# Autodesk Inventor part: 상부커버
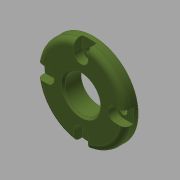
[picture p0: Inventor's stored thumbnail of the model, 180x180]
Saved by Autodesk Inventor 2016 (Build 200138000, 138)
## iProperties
Created: 2019-01
Part Number: 상부커버
Material: 알루미늄 6061
Document SubType Name: Modeling
Designer: mduedu
Density: 2.71 g/cm^3
Appearance: 올리브 녹색
Mass: 28.8858 g
Surface Area: 53.2237 cm^2
Volume: 10.659 cm^3
Author: mduedu
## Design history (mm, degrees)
sketch "스케치1"
  geometry: L1 (0, 0)-(7, 0); L2 (7, 0)-(7, 25); L3 (7, 25)-(0, 25); L4 (0, 25)-(0, 0); L5 (7, 0)-(10, 0); L6 (10, 0)-(10, 14); L7 (10, 14)-(7, 14); L8 (7, 14)-(7, 0)
  constraints: 16 end point, 4 parallel, 2 horizontal, 2 perpendicular
  dimensions: "d0" = 50 diameter of L3 L1; "d2" = 10 distance between parallel lines of L6 L4; "d3" = 7 distance of L2.end L3.end; "d4" = 28 diameter of L7 L5
revolve "회전1" sketch "스케치1" stored, may be unused: angle "d5" = 90 deg
sketch "스케치2"
  geometry: C1 r 10 at (0, 0); 1 further point
  constraints: 1 centre point, 1 coincident
  dimensions: "d6" = 20 diameter of C1
extrude "돌출1" cut sketch "스케치2" stored distance "d7" = 10; taper "d8" = 0 deg
chamfer "모따기1" distance "d9" = 1; stored, may be unused: second distance "d10" = 2, angle "d11" = 45 deg
fillet "모깎기1" dims "d12" = 3
sketch "스케치3" dims "d13" = 38
  geometry: 6 further points
  constraints: 2 vertical alignment, 1 coincident, 7 other
  dimensions: "d16" = 360 deg dimension on point (0, 0) point (0, 19) (derived)
chamfer "모따기2" distance "d18" = 1; stored, may be unused: second distance "d19" = 2, angle "d20" = 45 deg
sketch "스케치4"
  geometry: 4 further points
  constraints: 4 other
hole "구멍1" sketch "스케치4" at (-19, 0), (0, -19), (19, 0), (0, 19) diameter "d21" = 4.5; stored, may be unused: countersink angle "d25" = 90 deg, drill point angle "d27" = 0 deg; dims "d22" = 6, "d23" = 8, "d24" = 4.6, "d26" = 8
sketch "스케치5"
  geometry: L1 (-4, 0)-(-4, 5.678); L2 (4, 0)-(4, 5.678); A1 r 4 centre (0, 0) between (-2.841, 2.816) and (2.841, 2.816) reference; A2 r 25 centre (0, -19) between (-4, 5.678) and (4, 5.678) reference; A3 r 4 centre (0, 0) between (-4, 0) and (4, 0); A4 r 25 centre (0, -19) between (4, 5.678) and (-4, 5.678); A5 r 4 centre (0, 0) between (4, 0) and (-4, 0); 1 further point
  constraints: 10 point on circle, 4 end point, 3 centre point, 2 coincident, 2 tangent, 1 parallel, 1 vertical
extrude "돌출2" cut sketch "스케치5" stored distance "d28" = 10; taper "d29" = 0 deg
node "솔리드1"
pattern_circular "원형 패턴1" dims angle "d31" = 360 deg
